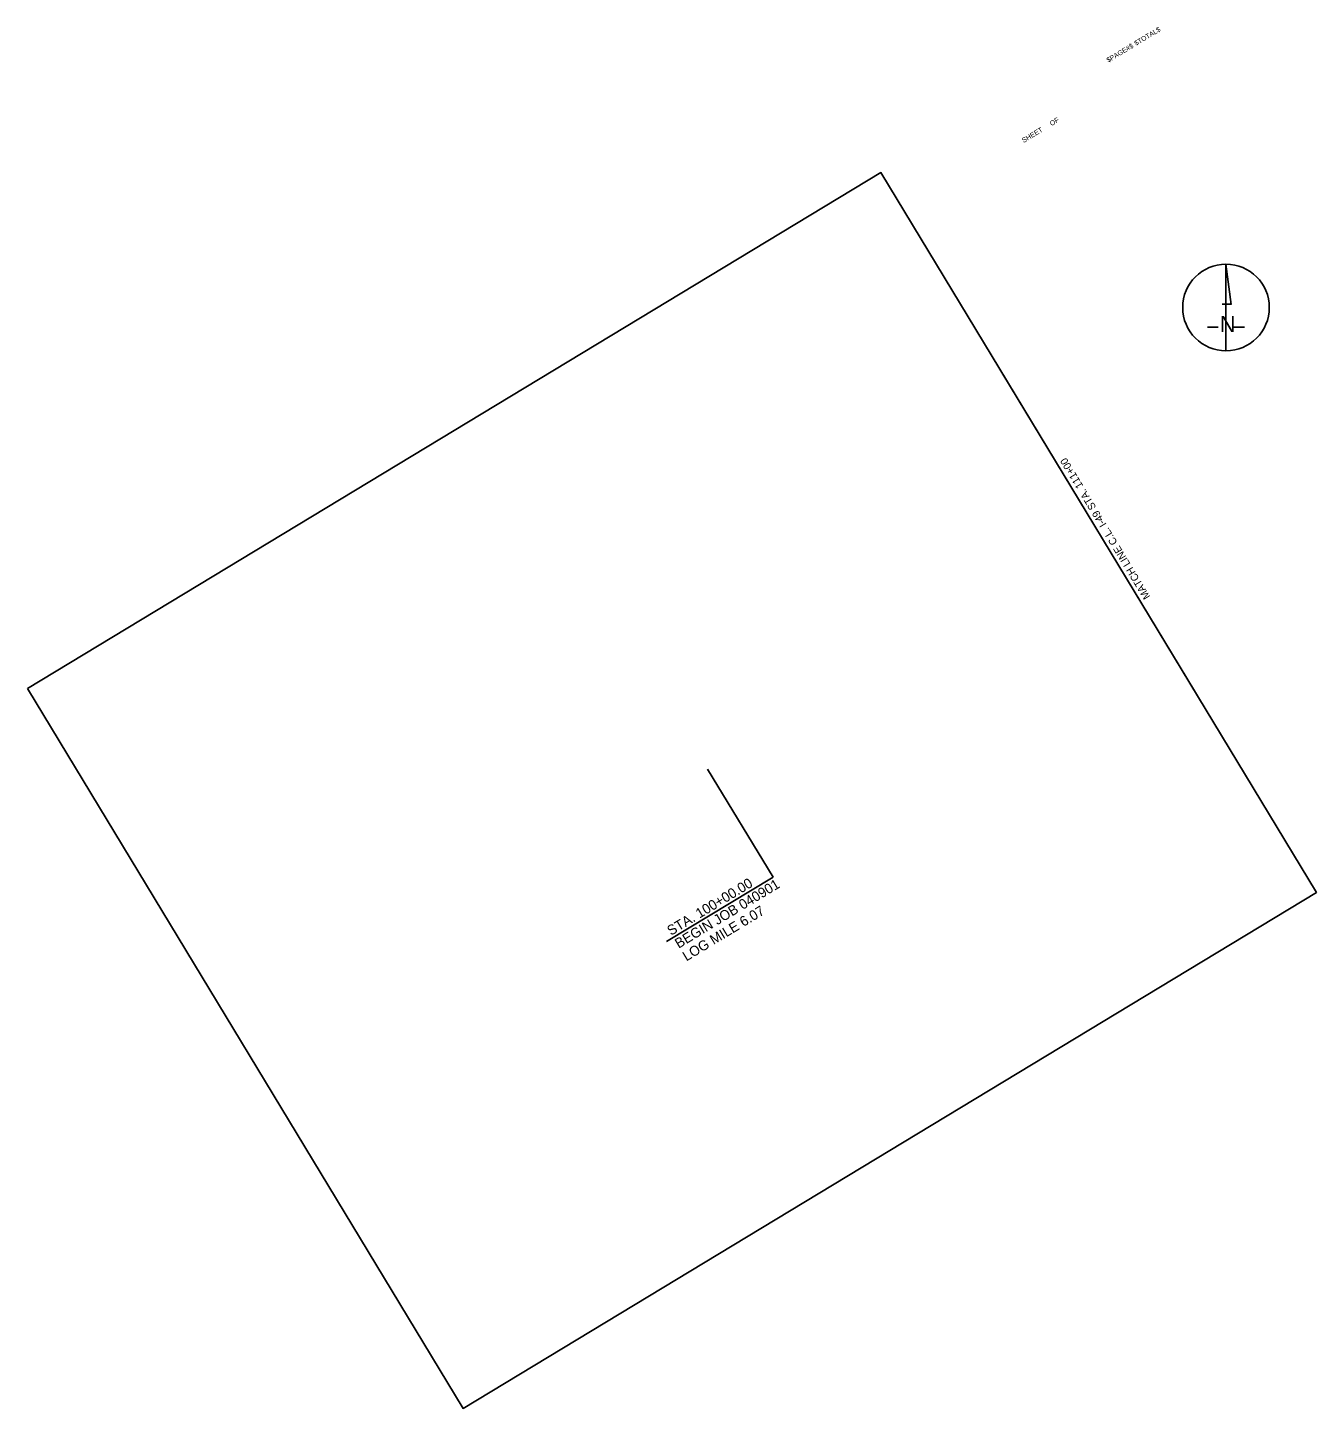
# Model space of a CAD drawing. Extents: x 627457 to 630558, y 366622 to 369946.
import ezdxf

# ---------------------------------------------------------------- set-up
doc = ezdxf.new("R2010")
doc.units = 0
for name, color, linetype in [('Copy of R_Dimension', 7, 'Continuous'), ('R_Border_N Arrow', 7, 'Continuous'), ('R_Draft', 7, 'Continuous'), ('S_DITCHLINE', 7, 'Continuous'), ('S_ELECTRIC_UTILITIES', 7, 'Continuous')]:
    doc.layers.add(name, color=color, linetype=linetype)

# ---------------------------------------------------------------- blocks, each defined once
blk = doc.blocks.new('SHT-INFO-CELL_2 TITLE LINES')
at = {"layer": 'Copy of R_Dimension'}
for s, p in [('SHEET', (14.441, 10.054)), ('OF', (14.833, 10.054))]:
    blk.add_text(s, height=0.06, dxfattribs=at).set_placement(p)

msp = doc.modelspace()

# ---------------------------------------------------------------- linework, layer by layer
at = {"layer": 'Copy of R_Dimension'}
for p, q in [((629510.2, 369597.3), (630558.2, 367864.4)), ((630340.7, 369376.8), (630340.7, 369168.5)), ((628504.6, 366622.4), (627456.6, 368355.4)), ((628504.6, 366622.4), (627456.6, 368355.4)), ((628504.6, 366622.4), (627456.6, 368355.4)), ((630558.2, 367864.4), (628504.6, 366622.4))]:
    msp.add_line(p, q, dxfattribs=at)
msp.add_lwpolyline([(627456.6, 368355.4), (629510.2, 369597.3), (630558.2, 367864.4), (628504.6, 366622.4)], close=True, dxfattribs=at)
msp.add_circle((630340.7, 369272.7), 104.2, dxfattribs=at)
at = {"layer": 'R_Border_N Arrow'}
for p, q in [((630340.7, 369376.8), (630352.9, 369279.9)), ((630340.7, 369241.2), (630340.7, 369376.8)), ((630331.3, 369280.6), (630352.9, 369280.6)), ((630296.1, 369225.3), (630321.9, 369225.3)), ((630340.7, 369168.5), (630340.7, 369208.4)), ((630357.8, 369225.3), (630385.3, 369225.3))]:
    msp.add_line(p, q, dxfattribs=at)
at = {"layer": 'R_Draft'}
msp.add_line((630267.1, 368345.8), (629801.4, 369115.9), dxfattribs=at)
at = {"layer": 'S_ELECTRIC_UTILITIES'}
for p, q in [((629093, 368161.6), (629250.5, 367901.1)), ((629250.5, 367901.1), (628994.2, 367746.1))]:
    msp.add_line(p, q, dxfattribs=at)

# ---------------------------------------------------------------- block references
at = {"layer": 'Copy of R_Dimension', "xscale": 199.99999999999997, "yscale": 200, "rotation": 31.16384373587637}
msp.add_blockref('SHT-INFO-CELL_2 TITLE LINES', (628423, 366453.3), dxfattribs=at)

# ---------------------------------------------------------------- texts
at = {"layer": 'R_Border_N Arrow'}
msp.add_text('N', height=38.8, rotation=360, dxfattribs=at).set_placement((630326, 369213.3))
at = {"layer": 'R_Draft'}
for s, p in [('$TOTAL$', (630124.4, 369902.4)), ('$PAGE#$', (630057.5, 369861.9))]:
    msp.add_text(s, height=11.72, rotation=31.1638, dxfattribs=at).set_placement(p)
at = {"layer": 'S_DITCHLINE'}
msp.add_text('MATCH LINE C.L. I-49 STA. 111+00', height=18, rotation=121.1638, dxfattribs=at).set_placement((630159.1, 368576.6))
at = {"layer": 'S_ELECTRIC_UTILITIES'}
for s, p in [('STA. 100+00.00', (629004.8, 367759.7)), ('BEGIN JOB 040901', (629023.4, 367728.9)), ('LOG MILE 6.07', (629042, 367698.1))]:
    msp.add_text(s, height=24, rotation=31.1638, dxfattribs=at).set_placement(p)

doc.saveas('drawing.dxf')
